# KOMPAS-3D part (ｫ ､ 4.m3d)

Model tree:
1. Эскиз:1
2. Операция выдавливания:1
     Расстояние 1 = 20
3. Эскиз:2
4. Операция выдавливания:2
     Расстояние 1 = 400
5. Эскиз:3
6. Вырезать элемент выдавливания:1
     Расстояние 1 = 70
7. Эскиз:4
8. Вырезать элемент выдавливания:2
     Расстояние 1 = 2
9. Эскиз:5
10. Эскиз:11
11. Вырезать элемент выдавливания:7
     Расстояние 1 = 30
12. Операция выдавливания:3
     Расстояние 1 = 16.96
13. Эскиз:13
14. Вырезать элемент выдавливания:9
     Расстояние 1 = 70
15. Эскиз:14
16. Вырезать элемент выдавливания:10
     Расстояние 1 = 80
